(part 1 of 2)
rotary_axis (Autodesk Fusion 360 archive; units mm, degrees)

design "assy_rotary_axis" references "rotary_barrel", "PP_TRNS_GT2-Pulley-20T-6mm", "HW_M5x10-FHCS", "PP_SWTC_Omron-V154", "HW_M3x8-FHCS", "HW_M3x16-SHCS", "circuit_mount_stepper_simple", "PP_BRNG_6808-40x52x7", "HW_M3x50-SHCS", "HW_M3-Washer", "PP_ACTU_N17-Stepper"
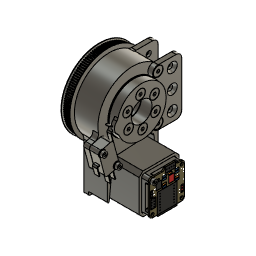
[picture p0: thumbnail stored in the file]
parameter "p_teeth" = 2
parameter "pd_pinion" = 12.7324 (= "nt_pinion * p_teeth / PI")
parameter "pd_drive" = 79.5775 (= "nt_drive * p_teeth / PI")
parameter "c_dist_manuel" = 58
parameter "d63" = 60
sketch "Sketch1" plane through (0, 0, 0) normal (0, 1, 0) x axis (1, 0, 0)
  line L1 (7, 26) -> (0, 26)
  line L2 (7, 20) -> (7, 26)
  line L3 (0, 20) -> (7, 20)
  line L4 (0, 26) -> (0, 20)
  line L5 (25, 20) -> (18, 20)
  line L6 (25, 26) -> (25, 20)
  line L7 (18, 26) -> (25, 26)
  line L8 (18, 20) -> (18, 26)
  line L9 (22.786, 0) -> (0, 0)
  line L10 (-50.1, 36.85) -> (19.9, 36.85)
  line L11 (-50.1, 79.15) -> (-50.1, 36.85)
  line L12 (19.9, 79.15) -> (-50.1, 79.15)
  line L13 (19.9, 36.85) -> (19.9, 79.15)
  line L14 (-50.1, 58) -> (19.9, 58)
  line L15 (25, 37.05) -> (25, 26.05)
  line L16 (0, 26.05) -> (25, 26.05)
  line L17 (25, 37.05) -> (0, 37.05)
  line L18 (0, 37.05) -> (0, 26.05)
  line L19 (7.5, 25.05) -> (6.5, 26.05)
  line L20 (17.5, 25.05) -> (7.5, 25.05)
  line L21 (18.5, 26.05) -> (17.5, 25.05)
  point P6 (18, 20)
  point P1 (0, 0)
  point P10 (0, 0)
  point P16 (19.9, 58)
  point P17 (-50.1, 58)
  point P21 (0, 37.05)
  point P23 (0, 37.05)
  point P18 (25, 26.05)
  point P19 (25, 26.05)
  point P8 (25, 26)
  point P2 (0, 26)
  point P24 (6.5, 26.05)
  point P27 (18.5, 26.05)
  point P4 (7, 20)
  point P5 (0, 20)
  point P12 (19.9, 36.85)
  point P15 (19.9, 79.15)
  point P13 (-50.1, 36.85)
  point P9 (18, 26)
  point P20 (0, 26.05)
  point P22 (25, 37.05)
  point P3 (7, 26)
  horizontal L1
  vertical L2
  horizontal L3
  horizontal L5
  vertical L6
  horizontal L7
  vertical L8
  equal L3 L5
  coincident L3 P6
  coincident P1 L4
  equal L2 L8
  coincident P1 P10
  horizontal L9
  horizontal L10
  vertical L11
  horizontal L12
  midpoint L13 P16
  midpoint L11 P17
  vertical L4
  vertical L15
  vertical L13
  perpendicular L2 L16
  perpendicular L13 L17
  perpendicular L10 L18
  coincident P21 P23
  coincident P18 P19
  coincident P8 L15
  coincident P2 L18
  coincident L16 P24
  parallel L1 L20
  coincident L16 P27
  dimension "d5" distance P4 P5 = 7
  dimension "d6" distance P1 L1 = 26 (= "( 52 / 2 ) * 1 mm")
  dimension "d7" distance P1 P5 = 20 (= "( 40 / 2 ) * 1 mm")
  dimension "d32" distance P12 P15 = 42.3
  dimension "d33" distance P1 P17 = 58 (= "c_dist_manuel")
  dimension "d34" distance P12 P13 = 70
  dimension "d61" distance P4 P6 = 11
  dimension "d140" distance P9 L16 = 0.05
  dimension "d141" distance P20 P23 = 11
  dimension "d150" distance L13 P22 = 5.1
  dimension "d259" angle L19 L20 = 45
  dimension "d260" distance P3 P24 = 0.5
  dimension "d261" distance L16 L20 = 1
  dimension "d262" angle L20 L21 = 45
  dimension "d263" distance L8 P27 = 0.5 (= "d260")
  dimension "d357" distance P18 L18 = 25
revolve "Revolve6" sketch "Sketch1" AlongAngle 360
sketch "Sketch6" plane through (0, 0, 0) normal (1, 0, 0) x axis (0, 1, 0)
  line L1 (21.15, -36.85) -> (-21.15, -36.85)
  line L2 (21.15, -79.15) -> (21.15, -36.85)
  line L3 (-21.15, -79.15) -> (21.15, -79.15)
  line L4 (-21.15, -36.85) -> (-21.15, -79.15)
  line L5 (21.15, -79.15) -> (-21.15, -36.85)
  line L6 (-21.15, -79.15) -> (21.15, -36.85)
  line L7 (0, 0) -> (0, -58)
  line L8 (15.5, -42.5) -> (-15.5, -42.5)
  line L9 (15.5, -73.5) -> (15.5, -42.5)
  line L10 (-15.5, -73.5) -> (15.5, -73.5)
  line L11 (-15.5, -42.5) -> (-15.5, -73.5)
  line L12 (15.4393, -40.5607) -> (-15.5, -42.5)
  line L13 (17.3786, -71.5) -> (-15.5, -42.5)
  line L14 (-13.5607, -73.4393) -> (-15.5, -42.5)
  line L15 (-15.5, -42.5) -> (12.1767, -76.5)
  line L16 (-15.5, -42.5) -> (-18.6616, -73.3384)
  line L17 (-15.5, -42.5) -> (15.3384, -45.6616)
  line L18 (12.4957, -82.7149) -> (-25.4068, -78.8291)
  line L19 (-21.0864, -36.6881) -> (-25.4068, -78.8291)
  line L20 (27, -33.674) -> (-21.0864, -36.6881)
  line L21 (-27, -78.6657) -> (-25.4068, -78.8291)
  line L22 (-27, -25.3713) -> (-27, -78.6657)
  line L23 (24.7149, -70.4957) -> (22.4249, -33.9608)
  line L24 (27, -25.3713) -> (27, -66.8875)
  line L25 (-43.1948, -16.2223) -> (-37.449, -37.6658)
  line L26 (-33.2458, -13.5564) -> (-43.1948, -16.2223)
  line L27 (-27.5, -35) -> (-33.2458, -13.5564)
  line L28 (-37.449, -37.6658) -> (-27.5, -35)
  line L29 (-46.8691, -14.101) -> (-39.5704, -41.3401)
  line L30 (-35.373, -11.0206) -> (-46.8691, -14.101)
  line L31 (-27, -37.9719) -> (-39.5704, -41.3401)
  arc A1 centre (-15.5, -42.5) radius 32.75 clockwise from (17.1859, -40.4512) to (17.0792, -45.8401)
  arc A2 centre (15.3384, -45.6616) radius 1.75 clockwise from (17.0792, -45.8401) to (13.5975, -45.4832)
  arc A3 centre (-15.5, -42.5) radius 29.25 clockwise from (13.6927, -40.6702) to (13.5975, -45.4832)
  arc A4 centre (15.4393, -40.5607) radius 1.75 clockwise from (13.6927, -40.6702) to (17.1859, -40.4512)
  arc A5 centre (-15.5, -42.5) radius 31 clockwise from (15.4393, -40.5607) to (15.3384, -45.6616)
  arc A6 centre (-15.5, -42.5) radius 33.0203 clockwise from (9.2638, -64.3425) to (5.3458, -68.1085)
  arc A7 centre (-1.6616, -59.5) radius 11.1 clockwise from (5.3458, -68.1085) to (-8.6691, -50.8915)
  arc A8 centre (-15.5, -42.5) radius 10.8203 clockwise from (-7.3852, -49.6575) to (-8.6691, -50.8915)
  arc A9 centre (0.9393, -57) radius 11.1 clockwise from (-7.3852, -49.6575) to (9.2638, -64.3425)
  arc A10 centre (-15.5, -42.5) radius 21.9203 clockwise from (0.9393, -57) to (-1.6616, -59.5)
  arc A11 centre (-15.5, -42.5) radius 45.5906 clockwise from (18.691, -72.6576) to (13.2815, -77.8572)
  arc A12 centre (12.1767, -76.5) radius 1.75 clockwise from (13.2815, -77.8572) to (11.0719, -75.1428)
  arc A13 centre (-15.5, -42.5) radius 42.0906 clockwise from (16.0661, -70.3424) to (11.0719, -75.1428)
  arc A14 centre (17.3786, -71.5) radius 1.75 clockwise from (16.0661, -70.3424) to (18.691, -72.6576)
  arc A15 centre (-15.5, -42.5) radius 43.8406 clockwise from (17.3786, -71.5) to (12.1767, -76.5)
  arc A16 centre (-15.5, -42.5) radius 32.75 clockwise from (-13.4512, -75.1859) to (-18.8401, -75.0792)
  arc A17 centre (-18.6616, -73.3384) radius 1.75 clockwise from (-18.8401, -75.0792) to (-18.4832, -71.5975)
  arc A18 centre (-15.5, -42.5) radius 29.25 clockwise from (-13.6702, -71.6927) to (-18.4832, -71.5975)
  arc A19 centre (-13.5607, -73.4393) radius 1.75 clockwise from (-13.6702, -71.6927) to (-13.4512, -75.1859)
  arc A20 centre (-15.5, -42.5) radius 31 clockwise from (-13.5607, -73.4393) to (-18.6616, -73.3384)
  circle C1 centre (-15.5, -42.5) radius 1.75
  arc A21 centre (-15.5, -42.5) radius 49 clockwise from (24.7149, -70.4957) to (12.4957, -82.7149)
  arc A22 centre (-15.5, -42.5) radius 49 clockwise from (27, -66.8875) to (24.7149, -70.4957)
  circle C2 centre (0, 0) radius 39.7887
  circle C3 centre (0, 0) radius 26.05
  circle C4 centre (0, 0) radius 37.05
  circle C5 centre (-27.5, -35) radius 1.25
  circle C6 centre (-43.1948, -16.2223) radius 1.25
  circle C7 centre (-43.1948, -16.2223) radius 3
  point P6 (0, -58)
  point P8 (0, -58)
  point P7 (0, 0)
  point P9 (0, 0)
  point P12 (15.5, -73.5)
  point P10 (-15.5, -42.5)
  point P13 (-15.5, -73.5)
  point P20 (-15.5, -42.5)
  point P27 (-15.5, -42.5)
  point P34 (-15.5, -42.5)
  point P41 (-15.5, -42.5)
  point P43 (-15.5, -42.5)
  point P18 (15.4393, -40.5607)
  point P44 (15.4393, -40.5607)
  point P42 (-15.5, -42.5)
  point P45 (-15.5, -42.5)
  point P32 (17.3786, -71.5)
  point P46 (17.3786, -71.5)
  point P47 (-15.5, -42.5)
  point P39 (-13.5607, -73.4393)
  point P48 (-13.5607, -73.4393)
  point P11 (15.5, -42.5)
  point P25 (0.9393, -57)
  point P33 (12.1767, -76.5)
  point P49 (12.1767, -76.5)
  point P50 (-15.5, -42.5)
  point P40 (-18.6616, -73.3384)
  point P51 (-18.6616, -73.3384)
  point P52 (-15.5, -42.5)
  point P19 (15.3384, -45.6616)
  point P53 (15.3384, -45.6616)
  point P54 (-15.5, -42.5)
  point P26 (-1.6616, -59.5)
  point P57 (-15.5, -42.5)
  point P60 (-21.0864, -36.6881)
  point P64 (22.4249, -33.9608)
  point P66 (19.1482, -77.1482)
  point P58 (24.7149, -70.4957)
  point P65 (24.7149, -70.4957)
  point P61 (27, -33.674)
  point P69 (-15.5, -42.5)
  point P67 (27, -66.8875)
  point P70 (27, -66.8875)
  point P71 (0, 0)
  point P68 (27, -25.3713)
  point P63 (-27, -25.3713)
  point P59 (-21.0864, -36.6881)
  point P76 (-27.5, -35)
  point P77 (-27.5, -35)
  point P74 (-43.1948, -16.2223)
  point P78 (-43.1948, -16.2223)
  point P80 (-35.373, -11.0206)
  point P83 (-27, -37.9719)
  point P4 (21.15, -79.15)
  point P5 (-21.15, -79.15)
  point P1 (0, 0)
  point P73 (-37.449, -37.6658)
  point P75 (-33.2458, -13.5564)
  point P81 (-43.1948, -16.2223)
  horizontal L1
  perpendicular L1 L2
  parallel L1 L3
  parallel L2 L4
  coincident L5 P6
  coincident L6 P6
  equal L2 L3
  coincident P6 P8
  coincident P7 P9
  vertical L7
  horizontal L8
  vertical L9
  horizontal L10
  vertical L11
  coincident L5 P12
  coincident L5 P10
  coincident L6 P13
  tangent A1 A2
  tangent A2 A3
  tangent A3 A4
  tangent A1 A4
  coincident P10 P20
  tangent A6 A7
  tangent A7 A8
  tangent A8 A9
  tangent A6 A9
  coincident P20 P27
  tangent A11 A12
  tangent A12 A13
  tangent A13 A14
  tangent A11 A14
  coincident P27 P34
  tangent A16 A17
  tangent A17 A18
  tangent A18 A19
  tangent A16 A19
  coincident P34 P41
  concentric A11 C1
  coincident P34 P43
  coincident P18 P44
  coincident P42 P45
  coincident P32 P46
  coincident P41 P47
  coincident P39 P48
  coincident P11 A5
  coincident P6 A10
  coincident P13 A20
  coincident P12 A15
  coincident P25 L13
  coincident P33 P49
  coincident P20 P50
  coincident P40 P51
  coincident P27 P52
  coincident P19 P53
  coincident P20 P54
  equal A4 A14
  equal A14 A19
  equal A19 C1
  coincident P26 L15
  perpendicular L12 L14
  perpendicular L16 L17
  parallel L17 L18
  coincident P42 P57
  parallel L16 L19
  coincident L19 P60
  parallel L12 L20
  perpendicular L19 L21
  vertical L22
  coincident L20 P64
  perpendicular L20 L23
  midpoint A21 P66
  coincident L5 P66
  coincident P58 P65
  vertical L24
  coincident P61 L24
  coincident P57 P69
  coincident P67 P70
  coincident P7 P71
  coincident P68 C4
  coincident P63 C4
  coincident P59 P60
  perpendicular L25 L26
  parallel L25 L27
  parallel L26 L28
  coincident P76 P77
  coincident P74 P78
  equal C5 C6
  perpendicular L26 L29
  coincident C4 P80
  perpendicular L29 L30
  concentric C6 C7
  coincident L22 P83
  perpendicular L29 L31
  dimension "d151" distance P6 P7 = 58 (= "c_dist_manuel")
  dimension "d152" distance P4 P5 = 42.3
  dimension "d153" distance P10 P11 = 31
  dimension "d154" diameter C1 = 3.5
  dimension "d156" radius A9 = 11.1 (= "( 22.2 / 2 ) * 1 mm")
  dimension "d157" distance P6 P25 = 1
  dimension "d158" distance P6 P26 = 1.5
  dimension "d159" angle L15 L17 = 45
  dimension "d160" radius A21 = 49
  dimension "d161" distance P40 L18 = 6.15 (= "( ( 42.3 - 31 ) / 2 ) * 1 mm + 0.5 mm")
  dimension "d162" distance L16 L19 = 6.15 (= "d161")
  dimension "d163" angle L12 L13 = 45
  dimension "d164" distance P20 L20 = 6.15 (= "d161")
  dimension "d166" distance P9 L22 = 27
  dimension "d167" distance P1 L24 = 27
  dimension "d264" diameter C2 = 79.5775 (= "pd_drive")
  dimension "d286" distance P73 P74 = 22.2
  dimension "d288" distance P74 P75 = 10.3
  dimension "d289" diameter C6 = 2.5
  dimension "d290" angle L7 L27 = 15
  dimension "d291" distance P71 P77 = 35
  dimension "d292" distance P1 P77 = 27.5
  dimension "d293" diameter C7 = 6
  dimension "d294" distance L29 P81 = 3
  dimension "d295" distance L30 P81 = 3 (= "d294")
  dimension "d303" distance P73 L31 = 3 (= "d294")
extrude "Extrude8" add sketch "Sketch6" profile of L19 L20 L21 L22 L23 L24 A22 C4 to an object
extrude "Extrude20" cut sketch "Sketch6" profile of L20 C4 to an object
extrude "Extrude19" add sketch "Sketch6" profile of A1 A2 A3 A4 A6 A7 A8 A9 A11 A12 A13 A14 A16 A17 A18 A19 C1 L18 A21 L19 L20 L23 along normal blind 5
chamfer "Chamfer4" distance 1.5
extrude "Extrude21" sketch "Sketch6" profile of L22 C4 C5 C6 L29 L30 L31 blind -6
extrude "Extrude22" sketch "Sketch6" profile of L22 C5 to an object offset 0.5
chamfer "Chamfer5" distance 1.25
chamfer "Chamfer6" distance 0.5
sketch "Sketch10" plane through (0, 0, 0) normal (-1, 0, 0) x axis (0, -1, 0)
  line L1 (27, -78.6657) -> (-12.4957, -82.7149)
  line L2 (27, -25.3713) -> (27, -78.6657)
  line L3 (-27, -66.8875) -> (-27, -25.3713)
  line L4 (-27, 50) -> (-47, 50)
  line L5 (-27, -90) -> (-27, 50)
  line L6 (-47, -90) -> (-27, -90)
  line L7 (-47, 50) -> (-47, -90)
  line L8 (-37, -90) -> (-37, 50)
  line L9 (-21.7417, 30) -> (-47, 30)
  line L10 (-47, -30) -> (-27, -30)
  line L11 (-18.6542, -30) -> (-27, -30)
  line L12 (-14.0196, -22.5467) -> (-18.6542, -30)
  line L13 (-27, 0) -> (0, 0)
  line L14 (-18.6542, 30) -> (-14.0196, 22.5467)
  line L15 (-21.7417, 30) -> (-18.6542, 30)
  circle C1 centre (15.5, -42.5) radius 3.25
  arc A1 centre (15.5, -42.5) radius 40.5906 clockwise from (-10.125, -73.9795) to (-14.9412, -69.3502)
  arc A2 centre (-12.1767, -76.5) radius 3.25 clockwise from (-10.125, -73.9795) to (-14.2284, -79.0205)
  arc A3 centre (15.5, -42.5) radius 47.0906 clockwise from (-14.2284, -79.0205) to (-19.8159, -73.6498)
  arc A4 centre (-17.3786, -71.5) radius 3.25 clockwise from (-19.8159, -73.6498) to (-14.9412, -69.3502)
  arc A5 centre (0, 0) radius 37.05 clockwise from (-27, -25.3713) to (27, -25.3713)
  arc A6 centre (15.5, -42.5) radius 49 clockwise from (-12.4957, -82.7149) to (-27, -66.8875)
  arc A7 centre (1.6616, -59.5) radius 11.1 clockwise from (8.6691, -50.8915) to (-5.3458, -68.1085)
  arc A8 centre (15.5, -42.5) radius 33.0203 clockwise from (-5.3458, -68.1085) to (-9.2638, -64.3425)
  arc A9 centre (-0.9393, -57) radius 11.1 clockwise from (-9.2638, -64.3425) to (7.3852, -49.6575)
  arc A10 centre (15.5, -42.5) radius 10.8203 clockwise from (8.6691, -50.8915) to (7.3852, -49.6575)
  arc A11 centre (15.5, -42.5) radius 27.75 clockwise from (-12.1053, -45.3302) to (-12.1956, -40.764)
  arc A12 centre (-15.3384, -45.6616) radius 3.25 clockwise from (-12.1053, -45.3302) to (-18.5714, -45.9931)
  arc A13 centre (15.5, -42.5) radius 34.25 clockwise from (-18.5714, -45.9931) to (-18.6829, -40.3574)
  arc A14 centre (-15.4393, -40.5607) radius 3.25 clockwise from (-18.6829, -40.3574) to (-12.1956, -40.764)
  arc A15 centre (13.5607, -73.4393) radius 3.25 clockwise from (13.3574, -76.6829) to (13.764, -70.1956)
  arc A16 centre (15.5, -42.5) radius 27.75 clockwise from (18.3302, -70.1053) to (13.764, -70.1956)
  arc A17 centre (18.6616, -73.3384) radius 3.25 clockwise from (18.3302, -70.1053) to (18.9931, -76.5714)
  arc A18 centre (15.5, -42.5) radius 34.25 clockwise from (18.9931, -76.5714) to (13.3574, -76.6829)
  circle C2 centre (0, 0) radius 26.55
  circle C3 centre (-37, -20) radius 2.75
  circle C4 centre (-37, 0) radius 2.75
  circle C5 centre (-37, 20) radius 2.75
  circle C6 centre (-21.9887, -24) radius 2.75
  circle C7 centre (-21.9887, -24) radius 2.2
  circle C8 centre (-21.9887, -24) radius 6
  circle C9 centre (-21.9887, 24) radius 2.75
  circle C10 centre (-21.9887, 24) radius 2.2
  circle C11 centre (-21.9887, 24) radius 6
  point P12 (-27, -25.3713)
  point P37 (-37, 50)
  point P38 (-37, -90)
  point P39 (-47, 30)
  point P40 (-21.7417, 30)
  point P41 (-27, -30)
  point P42 (-47, -30)
  point P43 (-37, -20)
  point P44 (-37, 0)
  point P45 (-37, 20)
  point P49 (-14.0196, -22.5467)
  point P1 (0, 0)
  point P50 (0, 0)
  point P51 (-27, 0)
  point P56 (-14.0196, 22.5467)
  point P58 (-21.7417, 30)
  point P33 (-47, 50)
  point P34 (-27, 50)
  point P13 (0, 0)
  horizontal L4
  vertical L5
  horizontal L6
  vertical L7
  coincident P12 L5
  midpoint L4 P37
  midpoint L6 P38
  coincident L7 P39
  coincident A5 P40
  perpendicular L7 L9
  coincident L5 P41
  coincident L7 P42
  perpendicular L7 L10
  coincident L8 P43
  coincident L8 P44
  coincident L8 P45
  equal C4 C5
  equal C3 C4
  concentric C6 C7
  perpendicular L5 L11
  coincident C2 P49
  coincident P1 L12
  coincident P1 P50
  coincident L5 P51
  perpendicular L5 L13
  concentric C7 C8
  equal C3 C6
  symmetric C6 L13 C9
  symmetric C7 L13 C10
  symmetric L13 C8 C11
  coincident C2 P56
  horizontal L15
  coincident P40 P58
  tangent C11 L14
  coincident P1 L14
  tangent L10 C8
  tangent C2 C8
  tangent L12 C8
  dimension "d358" distance P33 P34 = 20
  dimension "d359" distance P13 L4 = 50
  dimension "d360" distance P13 L6 = 90
  dimension "d361" distance P13 P39 = 30
  dimension "d368" diameter C3 = 5.5
  dimension "d369" distance P43 P44 = 20
  dimension "d370" distance P44 P45 = 20
  dimension "d371" distance P39 P45 = 10
  dimension "d372" distance L10 P43 = 10
  dimension "d375" angle L12 L13 = 58.126
  dimension "d376" diameter C7 = 4.4
  dimension "d377" diameter C8 = 12
extrude "Extrude23" cut sketch "Sketch10" profile of A5 L3 L5 L7 L9 L10 no distance stored from offset -5
extrude "Extrude24" add sketch "Sketch10" profile of A5 L3 L5 L7 L9 L10 C3 C4 C5 against normal blind 5
extrude "Extrude25" cut sketch "Sketch10" profile of A5 C3 C4 C5 no distance stored
chamfer "Chamfer7" distance 2.5
extrude "Extrude26" cut sketch "Sketch10" profile of C7 C10 no distance stored
extrude "Extrude27" sketch "Sketch10" profile of A5 L3 C2 L5 L7 L9 L10 C3 C4 C5 C6 L11 L12 C9 L14 L15 blind -5 from offset -0.1 bodies "rotary_body_cap"
chamfer "Chamfer8" distance 2.5
chamfer "Chamfer9" distance 2.5
fillet "Fillet18" radius 6
fillet "Fillet19" radius 6
component_insert "Component Insert9"
component_insert "Component Insert10"
joint "Assemble7" alignAngle 180 alignOffsetX 0 alignOffsetY 0 alignOffsetZ 0
joint "Assemble8" alignAngle 180 alignOffsetX 0 alignOffsetY 0 alignOffsetZ 0
component_insert "Component Insert1"
joint "Assemble1" alignAngle 0 alignOffsetX 0 alignOffsetY 0 alignOffsetZ 0
component_insert "Component Insert6"
joint "Assemble4" alignAngle 180 alignOffsetX 0 alignOffsetY 0 alignOffsetZ 0
component_insert "Component Insert7"
joint "Assemble5" alignAngle -195 alignOffsetX 0 alignOffsetY 0 alignOffsetZ 0
component_insert "Component Insert8"
joint "Assemble6" alignAngle 0 alignOffsetX 0 alignOffsetY 0 alignOffsetZ -2.5
component_insert "Component Insert11"
component_insert "Component Insert12"
component_insert "Component Insert13"
component_insert "Component Insert14"
joint "Assemble9" alignAngle 180 alignOffsetX 0 alignOffsetY 0 alignOffsetZ 0
joint "Assemble10" alignAngle 180 alignOffsetX 0 alignOffsetY 0 alignOffsetZ -5
joint "Assemble11" alignAngle 180 alignOffsetX 0 alignOffsetY 0 alignOffsetZ -5
joint "Assemble12" alignAngle 180 alignOffsetX 0 alignOffsetY 0 alignOffsetZ -5
component_insert "Component Insert15"
component_insert "Component Insert16"
joint "Assemble13" alignAngle 0 alignOffsetX 0 alignOffsetY 0 alignOffsetZ 0
joint "Assemble14" alignAngle 0 alignOffsetX 0 alignOffsetY 0 alignOffsetZ 0
component_insert "Component Insert17"
component_insert "Component Insert18"
joint "Assemble15" alignAngle 0 alignOffsetX 0 alignOffsetY 0 alignOffsetZ 0
joint "Assemble16" alignAngle 0 alignOffsetX 0 alignOffsetY 0 alignOffsetZ 0
fillet "Fillet10" radius 4
fillet "Fillet11" radius 10
fillet "Fillet12" radius 1
fillet "Fillet13" radius 5
fillet "Fillet14" radius 1
fillet "Fillet15" radius 1
fillet "Fillet16" radius 3
fillet "Fillet17" radius 5
fillet "Fillet20" radius 6
component_insert "Component Insert19"
joint "Assemble17" alignAngle 90 alignOffsetX 0 alignOffsetY 0 alignOffsetZ 0
component_insert "Component Insert20"
component_insert "Component Insert21"
joint "Assemble18" alignAngle 0 alignOffsetX 0 alignOffsetY 0 alignOffsetZ 0
joint "Assemble19" alignAngle 0 alignOffsetX 0 alignOffsetY 0 alignOffsetZ 0
component_insert "Component Insert23"
joint "Assemble20" alignAngle 90 alignOffsetX 0 alignOffsetY 0 alignOffsetZ 0
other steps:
joint_origin "JointOrigin5"
joint_origin "JointOrigin6"
joint_origin "JointOrigin9"
joint_origin "JointOrigin10"
joint_origin "JointOrigin11"
joint_origin "JointOrigin12"
joint_origin "JointOrigin13"
joint_origin "JointOrigin14"
named bodies: "rotary_body", "rotary_body_cap"

design "rotary_barrel" references "HW_M5x20-FHCS"
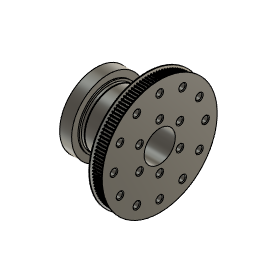
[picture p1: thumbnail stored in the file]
parameter "p_teeth" = 2
parameter "pd_pinion" = 12.7324 (= "nt_pinion * p_teeth / PI")
parameter "pd_drive" = 79.5775 (= "nt_drive * p_teeth / PI")
parameter "c_dist_manuel" = 75
sketch "Sketch1" plane through (0, 0, 0) normal (0, 1, 0) x axis (1, 0, 0)
  line L1 (7, 26) -> (0, 26)
  line L2 (7, 20) -> (7, 26)
  line L3 (0, 20) -> (7, 20)
  line L4 (0, 26) -> (0, 20)
  line L5 (25, 20) -> (18, 20)
  line L6 (25, 26) -> (25, 20)
  line L7 (18, 26) -> (25, 26)
  line L8 (18, 20) -> (18, 26)
  line L9 (35.5, 11.05) -> (2.5, 11.05)
  line L10 (35.5, 39.7887) -> (26, 39.7887)
  line L11 (26, 21.5) -> (25, 21.5)
  line L12 (26, 40.7887) -> (26, 21.5)
  line L13 (26.5, 40.7887) -> (26, 40.7887)
  line L14 (27.9434, 38.2887) -> (26.5, 40.7887)
  line L15 (33.5566, 38.2887) -> (27.9434, 38.2887)
  line L16 (35, 40.7887) -> (33.5566, 38.2887)
  line L17 (30.75, 38.2887) -> (30.75, 39.7887)
  line L18 (35, 38.2887) -> (35, 40.7887)
  line L19 (33.5566, 38.2887) -> (35, 38.2887)
  line L20 (26, 38.2887) -> (27.9434, 38.2887)
  line L21 (25, 20.05) -> (25, 21.5)
  line L22 (2.5, 20.05) -> (25, 20.05)
  line L23 (2.5, 11.05) -> (2.5, 20.05)
  line L24 (26, 38.2887) -> (26, 21.5)
  line L25 (35.5, 11.05) -> (35.5, 39.7887)
  line L26 (2, 11.05) -> (2, 20.05)
  line L27 (-9.5, 11.05) -> (2, 11.05)
  line L28 (-9.5, 26) -> (-9.5, 11.05)
  line L29 (-1, 26) -> (-9.5, 26)
  line L30 (-1, 21.5) -> (-1, 26)
  line L31 (0, 21.5) -> (-1, 21.5)
  line L32 (0, 20.05) -> (0, 21.5)
  line L33 (2, 20.05) -> (0, 20.05)
  line L34 (35.5, 40.7887) -> (35, 40.7887)
  line L35 (35.5, 39.7887) -> (35.5, 40.7887)
  line L36 (35.5, 14.35) -> (2.5, 14.35)
  line L37 (2.5, 16.55) -> (35.5, 16.55)
  line L38 (-9.5, 16.55) -> (2, 16.55)
  line L39 (-7.025, 13.925) -> (-9.5, 11.45)
  line L40 (2, 13.925) -> (-7.025, 13.925)
  line L41 (26, 32.5) -> (35.5, 32.5)
  line L42 (35.5, 34.7) -> (26, 34.7)
  point P6 (18, 20)
  point P1 (0, 0)
  point P13 (25, 21.5)
  point P20 (30.75, 39.7887)
  point P21 (30.75, 38.2887)
  point P11 (26, 39.7887)
  point P22 (27.2217, 39.5387)
  point P23 (34.2783, 39.5387)
  point P18 (33.5566, 38.2887)
  point P25 (33.5566, 38.2887)
  point P26 (26, 38.2887)
  point P27 (25, 20.05)
  point P10 (35.5, 11.05)
  point P30 (35.5, 11.05)
  point P31 (2, 20.05)
  point P39 (2, 20.05)
  point P32 (2, 11.05)
  point P5 (0, 20)
  point P12 (35.5, 39.7887)
  point P41 (35.5, 39.7887)
  point P42 (2.5, 14.35)
  point P45 (2.5, 16.55)
  point P46 (2, 16.55)
  point P47 (-9.5, 16.55)
  point P48 (-9.5, 11.45)
  point P50 (2, 13.925)
  point P51 (35.5, 32.5)
  point P54 (35.5, 34.7)
  point P53 (26, 34.7)
  point P52 (26, 32.5)
  point P44 (35.5, 16.55)
  point P43 (35.5, 14.35)
  point P4 (7, 20)
  point P14 (26, 21.5)
  point P15 (26, 40.7887)
  point P16 (26.5, 40.7887)
  point P7 (25, 20)
  point P3 (7, 26)
  point P9 (18, 26)
  point P28 (2.5, 20.05)
  point P29 (2.5, 11.05)
  point P36 (-1, 21.5)
  point P37 (0, 21.5)
  point P19 (35, 40.7887)
  point P40 (35.5, 40.7887)
  point P33 (-9.5, 11.05)
  point P38 (0, 20.05)
  horizontal L1
  vertical L2
  horizontal L3
  horizontal L5
  vertical L6
  horizontal L7
  vertical L8
  equal L3 L5
  coincident L3 P6
  coincident P1 L4
  equal L2 L8
  horizontal L9
  vertical L4
  horizontal L10
  coincident L6 P13
  perpendicular L6 L11
  perpendicular L10 L12
  perpendicular L12 L13
  perpendicular L12 L15
  midpoint L10 P20
  midpoint L15 P21
  vertical L17
  coincident P11 L12
  midpoint L14 P22
  midpoint L16 P23
  perpendicular L18 L19
  coincident P18 P25
  coincident L12 P26
  perpendicular L12 L20
  coincident L6 P27
  perpendicular L4 L22
  perpendicular L9 L23
  equal L14 L16
  vertical L18
  perpendicular L10 L25
  coincident P10 P30
  perpendicular L5 L26
  perpendicular L9 L28
  perpendicular L28 L29
  perpendicular L29 L30
  perpendicular L30 L31
  perpendicular L31 L32
  perpendicular L30 L33
  coincident P31 P39
  coincident L22 P31
  coincident L9 P32
  coincident P5 L32
  coincident P13 L31
  horizontal L27
  perpendicular L18 L34
  perpendicular L34 L35
  coincident P12 P41
  coincident L23 P42
  perpendicular L23 L36
  coincident L23 P45
  perpendicular L23 L37
  coincident L26 P46
  coincident L28 P47
  perpendicular L28 L38
  coincident L28 P48
  coincident L26 P50
  perpendicular L26 L40
  coincident P45 L38
  coincident L25 P51
  perpendicular L25 L41
  coincident L25 P54
  perpendicular L25 L42
  coincident L12 P53
  coincident L12 P52
  coincident L25 P44
  coincident L25 P43
  dimension "d5" distance P4 P5 = 7
  dimension "d6" distance P1 L1 = 26 (= "( 52 / 2 ) * 1 mm")
  dimension "d7" distance P1 P5 = 20 (= "( 40 / 2 ) * 1 mm")
  dimension "d62" distance P1 L10 = 39.7887 (= "pd_drive / 2")
  dimension "d63" angle L13 L14 = 60
  dimension "d66" distance P13 P14 = 1
  dimension "d67" distance L10 L13 = 1
  dimension "d68" distance L10 L15 = 1.5
  dimension "d69" distance P15 P16 = 0.5
  dimension "d71" distance P7 L11 = 1.5
  dimension "d72" distance P6 L22 = 0.05
  dimension "d81" angle L15 L16 = 120 (= "180 deg - d63")
  dimension "d133" distance P15 L18 = 9
  dimension "d223" distance P3 P9 = 11
  dimension "d224" distance L23 P32 = 0.5
  dimension "d225" distance P28 P29 = 9
  dimension "d227" distance P36 P37 = 1
  dimension "d228" distance P1 L29 = 26 (= "( 52 / 2 ) * 1 mm")
  dimension "d229" distance P19 P40 = 0.5
  dimension "d237" distance P10 L28 = 45
  dimension "d238" distance P32 P33 = 11.5
  dimension "d240" distance L36 P45 = 2.2 (= "( 4.4 / 2 ) * 1 mm")
  dimension "d242" distance L38 L40 = 2.625 (= "( 5.25 / 2 ) * 1 mm")
  dimension "d243" angle L39 L40 = 45
  dimension "d244" distance P47 P48 = 5.1 (= "( 10.2 / 2 ) * 1 mm")
  dimension "d245" distance P33 L38 = 5.5
  dimension "d250" distance L41 P54 = 2.2 (= "( 4.4 / 2 ) * 1 mm")
  dimension "d251" distance P1 L41 = 32.5
  dimension "d307" distance P13 P37 = 25
  dimension "d308" distance L26 P38 = 2
revolve "Revolve1" sketch "Sketch1" AlongAngle 360 bodies "rotary_barrel_toothed", "rotary_barrel_cap"
sketch "Sketch5" plane through (26, 0, 0) normal (-1, 0, 0) x axis (0, -1, 0)
  line L1 (0, -39.7887) -> (0, 0)
  line L2 (-0.9999, -39.7762) -> (0, 0)
  circle C1 centre (0, 0) radius 21.5
  circle C2 centre (0, 0) radius 39.7887
  circle C3 centre (0, 0) radius 39.5347
  arc A1 centre (0, -39.3347) radius 0.55 clockwise from (-0.4889, -39.0828) to (0, -38.7847)
  arc A2 centre (0.4, -39.5409) radius 1 clockwise from (-0.5899, -39.3991) to (-0.4889, -39.0828)
  arc A3 centre (-0.7384, -39.3778) radius 0.15 clockwise from (-0.5899, -39.3991) to (-0.7412, -39.5278)
  point P1 (0, 0)
  point P4 (0, 0)
  point P5 (0, -39.7887)
  point P3 (0, 0)
  point P6 (0, 0)
  point P7 (-0.9999, -39.7762)
  point P9 (0, -38.7847)
  point P13 (-0.7412, -39.5278)
  point P15 (0, -39.5347)
  point P8 (0, -39.3347)
  point P11 (0.4, -39.5409)
  concentric C1 C3
  coincident P1 P4
  coincident C2 P5
  vertical L1
  coincident P3 P6
  coincident C2 P7
  coincident L1 P9
  tangent A1 A2
  tangent A2 A3
  coincident C3 P13
  coincident L1 P15
  coincident C3 P15
  coincident L1 P8
  tangent C3 A3
  dimension "d116" distance C2 C3 = 0.254
  dimension "d117" angle L1 L2 = 1.44 (= "( 180 / nt_drive ) * 1 deg")
  dimension "d118" radius A1 = 0.55
  dimension "d119" radius A2 = 1
  dimension "d120" distance L1 P11 = 0.4
  dimension "d121" radius A3 = 0.15
  dimension "d122" distance P9 P15 = 0.75
extrude "Extrude6" new body sketch "Sketch5" profile of C2 C3 L1 L2 A1 A2 A3 to an object
offset_faces "OffsetFaces1" distance 0.05
mirror "Mirror2" mirrorStitchTolerance 0.1
circular_pattern "C-Pattern3" TotalAngle 360
combine "Combine3"
combine "Combine4"
revolve "Revolve5" sketch "Sketch1" AlongAngle 360
sketch "Sketch8" plane through (-9.5, 0, 0) normal (-1, 0, 0) x axis (0, -1, 0)
  line L1 (-29, 0) -> (0, 0)
  circle C1 centre (0, 0) radius 11.05
  circle C2 centre (0, 0) radius 26
  arc A1 centre (-21, 0) radius 8 clockwise from (-25.0714, -6.8865) to (-25.0714, 6.8865)
  point P4 (-25.0714, 6.8865)
  point P3 (-25.0714, -6.8865)
  point P1 (0, 0)
  point P6 (0, 0)
  point P8 (-26, 0)
  point P7 (-29, 0)
  point P5 (-21, 0)
  coincident C2 P4
  coincident C2 P3
  coincident P1 P6
  horizontal L1
  coincident L1 P8
  coincident C2 P8
  coincident A1 P7
  coincident P5 L1
  dimension "d231" distance P7 P8 = 3
  dimension "d232" radius A1 = 8
extrude "Extrude13" add sketch "Sketch8" profile of C2 A1 against normal blind 3.6
fillet "Fillet2" radius 5
revolve "Revolve7" sketch "Sketch1" AlongAngle 360
chamfer "Chamfer4" distance 0.5
circular_pattern "C-Pattern9" TotalAngle 360
revolve "Revolve8" sketch "Sketch1" AlongAngle 360
chamfer "Chamfer3" distance 0.5
circular_pattern "C-Pattern8" countU 12 TotalAngle 360
component_insert "Component Insert8"
component_insert "Component Insert9"
component_insert "Component Insert10"
component_insert "Component Insert11"
component_insert "Component Insert12"
component_insert "Component Insert13"
joint "Assemble19" alignAngle 0 alignOffsetX 0 alignOffsetY 0 alignOffsetZ 0
joint "Assemble20" alignAngle 0 alignOffsetX 0 alignOffsetY 0 alignOffsetZ 0
joint "Assemble21" alignAngle 0 alignOffsetX 0 alignOffsetY 0 alignOffsetZ 0
joint "Assemble22" alignAngle 0 alignOffsetX 0 alignOffsetY 0 alignOffsetZ 0
joint "Assemble23" alignAngle 0 alignOffsetX 0 alignOffsetY 0 alignOffsetZ 0
joint "Assemble24" alignAngle 0 alignOffsetX 0 alignOffsetY 0 alignOffsetZ 0
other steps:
joint_origin "JointOrigin19"
joint_origin "JointOrigin20"
joint_origin "JointOrigin22"
joint_origin "JointOrigin23"
joint_origin "JointOrigin24"
joint_origin "JointOrigin25"
named bodies: "rotary_barrel_toothed", "rotary_barrel_cap"

design "HW_M5x10-FHCS"
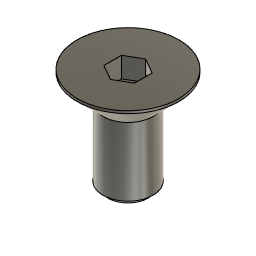
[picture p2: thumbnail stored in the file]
sketch "Sketch1" plane through (0, 0, 0) normal (0, 1, 0) x axis (1, 0, 0)
  line L1 (0, 10) -> (0, 0)
  line L2 (1.95, 10) -> (0, 10)
  line L3 (2.45, 9.5) -> (1.95, 10)
  line L4 (2.45, 2.8) -> (2.45, 9.5)
  line L5 (5, 0.25) -> (2.45, 2.8)
  line L6 (5, 0) -> (5, 0.25)
  line L7 (0, 0) -> (5, 0)
  point P1 (0, 0)
  point P2 (0, 0)
  point P9 (0, 0)
  point P3 (0, 10)
  point P4 (1.95, 10)
  point P8 (5, 0)
  point P7 (5, 0.25)
  coincident P1 P2
  vertical L1
  perpendicular L1 L2
  perpendicular L2 L4
  parallel L3 L5
  parallel L4 L6
  perpendicular L6 L7
  coincident P1 P9
  dimension "d1" distance P3 L4 = 2.45 (= "( 4.9 / 2 ) * 1 mm")
  dimension "d3" angle L2 L3 = 45
  dimension "d5" distance P4 L4 = 0.5
  dimension "d6" distance P2 P3 = 10
  dimension "d7" distance P8 P9 = 5 (= "( 10 / 2 ) * 1 mm")
  dimension "d9" distance P7 P8 = 0.25
revolve "Revolve1" sketch "Sketch1" AlongAngle 360
sketch "Sketch2" plane through (0, 0, 0) normal (0, 0, 1) x axis (-1, 0, 0)
  line L1 (0, -1.7321) -> (-1.5, -0.866)
  line L2 (1.5, -0.866) -> (0, -1.7321)
  line L3 (1.5, 0.866) -> (1.5, -0.866)
  line L4 (0, 1.7321) -> (1.5, 0.866)
  line L5 (-1.5, 0.866) -> (0, 1.7321)
  line L6 (-1.5, -0.866) -> (-1.5, 0.866)
  circle C1 centre (0, 0) radius 5
  point P1 (0, 0)
  point P9 (0, 0)
  coincident P1 P9
  vertical L6
  dimension "d12" distance L3 L6 = 3
extrude "Extrude1" cut sketch "Sketch2" profile of L1 L2 L3 L4 L5 L6 against normal blind 2

design "HW_M3x8-FHCS"
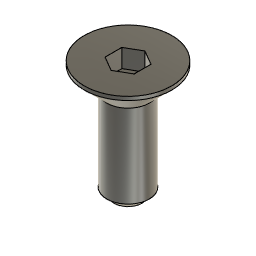
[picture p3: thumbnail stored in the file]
sketch "Sketch1" plane through (0, 0, 0) normal (0, 1, 0) x axis (1, 0, 0)
  line L1 (0, 8) -> (0, 0)
  line L2 (0.95, 8) -> (0, 8)
  line L3 (1.45, 7.5) -> (0.95, 8)
  line L4 (1.45, 1.8) -> (1.45, 7.5)
  line L5 (3, 0.25) -> (1.45, 1.8)
  line L6 (3, 0) -> (3, 0.25)
  line L7 (0, 0) -> (3, 0)
  point P1 (0, 0)
  point P2 (0, 0)
  point P9 (0, 0)
  point P3 (0, 8)
  point P4 (0.95, 8)
  point P8 (3, 0)
  point P7 (3, 0.25)
  coincident P1 P2
  vertical L1
  perpendicular L1 L2
  perpendicular L2 L4
  parallel L3 L5
  parallel L4 L6
  perpendicular L6 L7
  coincident P1 P9
  dimension "d1" distance P3 L4 = 1.45 (= "( 2.9 / 2 ) * 1 mm")
  dimension "d3" angle L2 L3 = 45
  dimension "d5" distance P4 L4 = 0.5
  dimension "d6" distance P2 P3 = 8
  dimension "d7" distance P8 P9 = 3 (= "( 6 / 2 ) * 1 mm")
  dimension "d9" distance P7 P8 = 0.25
revolve "Revolve1" sketch "Sketch1" AlongAngle 360
sketch "Sketch2" plane through (0, 0, 0) normal (0, 0, 1) x axis (-1, 0, 0)
  line L1 (0, -1.1547) -> (-1, -0.5774)
  line L2 (1, -0.5774) -> (0, -1.1547)
  line L3 (1, 0.5774) -> (1, -0.5774)
  line L4 (0, 1.1547) -> (1, 0.5774)
  line L5 (-1, 0.5774) -> (0, 1.1547)
  line L6 (-1, -0.5774) -> (-1, 0.5774)
  circle C1 centre (0, 0) radius 3
  point P1 (0, 0)
  point P9 (0, 0)
  coincident P1 P9
  vertical L6
  dimension "d12" distance L3 L6 = 2
extrude "Extrude1" cut sketch "Sketch2" profile of L1 L2 L3 L4 L5 L6 against normal blind 1.26

design "circuit_modular_stepper"
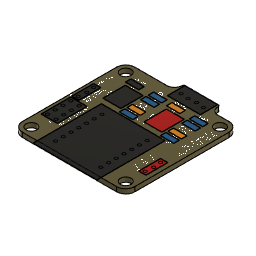
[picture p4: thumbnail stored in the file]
sketch "Outline" plane through (0, 0, 0) normal (0, 0, 1) x axis (1, 0, 0)
  line L1 (35, 1) -> (4, 1)
  line L2 (38, 35) -> (38, 4)
  line L3 (31, 38) -> (35, 38)
  line L4 (17.5, 41) -> (28.5, 41)
  line L5 (4, 38) -> (14.5, 38)
  line L6 (1, 4) -> (1, 35)
  arc A1 centre (4, 4) radius 3 clockwise from (4, 1) to (1, 4)
  arc A2 centre (35, 4) radius 3 clockwise from (38, 4) to (35, 1)
  arc A3 centre (35, 35) radius 3 clockwise from (35, 38) to (38, 35)
  arc A4 centre (31.25, 40.25) radius 2.2638 clockwise from (31, 38) to (29, 40.5)
  arc A5 centre (28.5, 40.5) radius 0.5 clockwise from (28.5, 41) to (29, 40.5)
  arc A6 centre (17.5, 40.5) radius 0.5 clockwise from (17, 40.5) to (17.5, 41)
  arc A7 centre (14.5, 40.5) radius 2.5 clockwise from (17, 40.5) to (14.5, 38)
  arc A8 centre (4, 35) radius 3 clockwise from (1, 35) to (4, 38)
canvas "Canvas1"
canvas "Canvas2"
pcbhole "PCBHole1" HoleDepth 1.606 HoleDiameter 3.5 TipAngle 10313.2
pcbhole "PCBHole2" HoleDepth 1.606 HoleDiameter 3.5 TipAngle 10313.2
pcbhole "PCBHole3" HoleDepth 1.606 HoleDiameter 3.5 TipAngle 10313.2
pcbhole "PCBHole4" HoleDepth 1.606 HoleDiameter 3.5 TipAngle 10313.2
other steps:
pcbextrude "PCBExtrude1"
pcbextrude "PCBExtrude1"
extrude "Extrude1" sketch "Outline" blind 1.5 bodies "Board"
box_primitive "BoxPrimitive1" DistanceX 7.1628 DistanceY 2.3368 DistanceZ 0.1 OffsetDistanceX 0 OffsetDistanceY 0
box_primitive "BoxPrimitive1" DistanceX 10.827 DistanceY 5.727 DistanceZ 0.1 OffsetDistanceX 0 OffsetDistanceY 0
box_primitive "BoxPrimitive1" DistanceX 5.353 DistanceY 9.7028 DistanceZ 0.1 OffsetDistanceX 0 OffsetDistanceY 0
box_primitive "BoxPrimitive1" DistanceX 4.4 DistanceY 1.8 DistanceZ 0.1 OffsetDistanceX 0 OffsetDistanceY 0
box_primitive "BoxPrimitive1" DistanceX 7.35 DistanceY 5.8597 DistanceZ 0.1 OffsetDistanceX 0 OffsetDistanceY 0
box_primitive "BoxPrimitive1" DistanceX 22.4638 DistanceY 20.955 DistanceZ 0.1 OffsetDistanceX 0 OffsetDistanceY 0
pcbextrude "PCBExtrude1"
pcbextrude "PCBExtrude2" bodies "CopperHoles"
create_component "CreateComponent1"
create_component "CreateComponent2"
create_component "CreateComponent3"
create_component "CreateComponent4"
create_component "CreateComponent1"
create_component "CreateComponent2"
create_component "CreateComponent3"
create_component "CreateComponent4"
create_component "CreateComponent5"
create_component "CreateComponent6"
as_built_joint "As-built1"
named bodies: "Board", "CopperHoles"

design "circuit_mount_stepper_simple" references "circuit_modular_stepper"
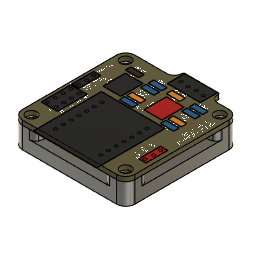
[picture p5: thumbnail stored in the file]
sketch "Sketch1" plane through (0, 0, 0) normal (0, 0, 1) x axis (1, 0, 0)
  line L1 (-18.5, 18.5) -> (18.5, 18.5)
  line L2 (-18.5, -18.5) -> (-18.5, 18.5)
  line L3 (18.5, -18.5) -> (-18.5, -18.5)
  line L4 (18.5, 18.5) -> (18.5, -18.5)
  line L5 (-18.5, -18.5) -> (18.5, 18.5)
  line L6 (18.5, -18.5) -> (-18.5, 18.5)
  line L7 (15.5, 15.5) -> (-15.5, 15.5)
  line L8 (15.5, -15.5) -> (15.5, 15.5)
  line L9 (-15.5, -15.5) -> (15.5, -15.5)
  line L10 (-15.5, 15.5) -> (-15.5, -15.5)
  circle C1 centre (15.5, 15.5) radius 1.7
  circle C2 centre (-15.5, 15.5) radius 1.7
  circle C3 centre (-15.5, -15.5) radius 1.7
  circle C4 centre (15.5, -15.5) radius 1.7
  circle C5 centre (-15.5, 15.5) radius 4.5
  circle C6 centre (15.5, 15.5) radius 4.5
  circle C7 centre (15.5, -15.5) radius 4.5
  circle C8 centre (-15.5, -15.5) radius 4.5
  circle C9 centre (0, 0) radius 15
  circle C10 centre (0, 0) radius 2.5
  circle C11 centre (0, 0) radius 4
  circle C12 centre (0, 0) radius 6.5
  point P6 (0, 0)
  point P1 (0, 0)
  point P9 (15.5, -15.5)
  point P7 (-15.5, 15.5)
  point P8 (15.5, 15.5)
  point P11 (15.5, 15.5)
  point P12 (-15.5, 15.5)
  point P10 (-15.5, -15.5)
  point P13 (-15.5, -15.5)
  point P14 (15.5, -15.5)
  point P19 (0, 0)
  point P21 (0, 0)
  point P2 (18.5, 18.5)
  point P3 (-18.5, 18.5)
  horizontal L1
  perpendicular L1 L2
  parallel L1 L3
  parallel L2 L4
  coincident L5 P6
  coincident L6 P6
  coincident P1 P6
  equal L1 L4
  horizontal L7
  vertical L8
  horizontal L9
  vertical L10
  coincident L6 P9
  coincident L6 P7
  coincident L5 P8
  equal C3 C4
  equal C1 C4
  equal C1 C2
  coincident P8 P11
  coincident P7 P12
  coincident P10 P13
  coincident P9 P14
  concentric C2 C5
  concentric C1 C6
  concentric C4 C7
  concentric C3 C8
  equal C5 C8
  equal C5 C6
  equal C6 C7
  coincident P1 P19
  concentric C9 C10
  coincident P1 P21
  concentric C9 C12
  dimension "d1" distance P7 P8 = 31
  dimension "d2" distance P2 P3 = 37
  dimension "d3" diameter C1 = 3.4
  dimension "d4" distance L4 P11 = 3
  dimension "d5" diameter C6 = 9
  dimension "d6" diameter C9 = 30
  dimension "d7" diameter C10 = 5
  dimension "d8" diameter C11 = 8
  dimension "d9" distance C11 C12 = 2.5
extrude "Extrude1" new body sketch "Sketch1" profile of L1 L2 L3 L4 C1 C2 C3 C4 C5 C6 C7 C8 along normal blind 7 bodies "circuit_mount_stepper_simple"
extrude "Extrude4" add sketch "Sketch1" profile of L1 L2 L3 L4 C5 C6 C7 C8 C9 to an object offset -3
chamfer "Chamfer4" distance 0.5
fillet "Fillet1" radius 3
fillet "Fillet2" radius 2
chamfer "Chamfer5" distance 0.5
component_insert "Component Insert"
joint "Assemble1" alignAngle 0 alignOffsetX 0 alignOffsetY 0 alignOffsetZ 0
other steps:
joint_origin "JointOrigin1"
named bodies: "circuit_mount_stepper_simple"

design "HW_M3x50-SHCS"
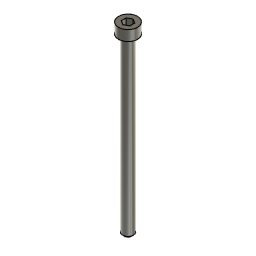
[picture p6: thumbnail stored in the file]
sketch "Sketch1" plane through (0, 0, 0) normal (0, 1, 0) x axis (1, 0, 0)
  line L1 (0, 50) -> (0, -3)
  line L2 (1.05, 50) -> (0, 50)
  line L3 (1.55, 49.5) -> (1.05, 50)
  line L4 (1.55, 0) -> (1.55, 49.5)
  line L5 (2.75, 0) -> (1.55, 0)
  line L6 (2.75, -3) -> (2.75, 0)
  line L7 (0, -3) -> (2.75, -3)
  point P1 (0, 0)
  point P4 (1.05, 50)
  point P5 (1.55, 49.5)
  point P3 (0, 50)
  point P7 (2.75, 0)
  point P8 (2.75, -3)
  point P2 (0, -3)
  vertical L1
  perpendicular L1 L2
  perpendicular L2 L4
  perpendicular L4 L5
  perpendicular L5 L6
  horizontal L7
  coincident P1 L1
  coincident P1 L5
  dimension "d1" distance P1 L2 = 50
  dimension "d2" angle L2 L3 = 45
  dimension "d3" distance P4 P5 = 0.5
  dimension "d4" distance P3 L4 = 1.55 (= "( 3.1 / 2 ) * 1 mm")
  dimension "d5" distance P7 P8 = 3
  dimension "d6" distance P2 P8 = 2.75 (= "( 5.5 / 2 ) * 1 mm")
revolve "Revolve1" sketch "Sketch1" AlongAngle 360
sketch "Sketch2" plane through (0, 0, 3) normal (0, 0, 1) x axis (-1, 0, 0)
  line L1 (0, -1.4434) -> (-1.25, -0.7217)
  line L2 (1.25, -0.7217) -> (0, -1.4434)
  line L3 (1.25, 0.7217) -> (1.25, -0.7217)
  line L4 (0, 1.4434) -> (1.25, 0.7217)
  line L5 (-1.25, 0.7217) -> (0, 1.4434)
  line L6 (-1.25, -0.7217) -> (-1.25, 0.7217)
  circle C1 centre (0, 0) radius 2.75
  point P1 (0, 0)
  point P9 (0, 0)
  point P5 (1.25, -0.7217)
  coincident P1 P9
  vertical L6
  dimension "d8" distance P5 L6 = 2.5
extrude "Extrude1" cut sketch "Sketch2" profile of L1 L2 L3 L4 L5 L6 against normal blind 2

design "PP_SWTC_Omron-V154"
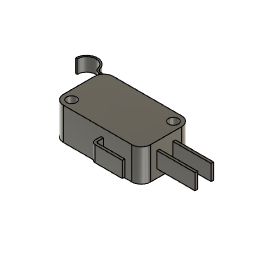
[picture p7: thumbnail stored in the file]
sketch "Sketch1" plane through (0, 0, 0) normal (0, 0, 1) x axis (1, 0, 0)
  line L1 (22.2, 0) -> (0, 0)
  line L2 (22.2, 10.3) -> (22.2, 0)
  line L3 (0, 10.3) -> (22.2, 10.3)
  line L4 (0, 0) -> (0, 10.3)
  line L5 (25, -2.8) -> (-2.8, -2.8)
  line L6 (25, 13.1) -> (25, -2.8)
  line L7 (-2.8, 13.1) -> (25, 13.1)
  line L8 (-2.8, -2.8) -> (-2.8, 13.1)
  line L9 (14.1, 15.2) -> (14.1, 13.1)
  line L10 (-6.9, 15.2) -> (14.1, 15.2)
  line L11 (13.6, 14.7) -> (-7.442, 14.7)
  line L12 (13.6, 13.1) -> (13.6, 14.7)
  line L13 (-13.9, 15.2) -> (-13.4, 15.2)
  line L14 (-10.4, 18.7) -> (-10.4, 15.2)
  line L15 (37.2, 8.1) -> (25, 8.1)
  line L16 (37.2, 7.3) -> (37.2, 8.1)
  line L17 (25, 7.3) -> (37.2, 7.3)
  line L18 (25, 8.1) -> (25, 7.3)
  line L19 (37.2, 3) -> (25, 3)
  line L20 (37.2, 2.2) -> (37.2, 3)
  line L21 (25, 2.2) -> (37.2, 2.2)
  line L22 (25, 3) -> (25, 2.2)
  line L23 (13, -5.2) -> (13, -2.8)
  line L24 (22.2, -5.2) -> (13, -5.2)
  line L25 (22.2, -6) -> (22.2, -5.2)
  line L26 (12.2, -6) -> (22.2, -6)
  line L27 (12.2, -2.8) -> (12.2, -6)
  circle C1 centre (0, 0) radius 2.8
  circle C2 centre (22.2, 10.3) radius 2.8
  circle C3 centre (22.2, 10.3) radius 1.55
  circle C4 centre (0, 0) radius 1.55
  arc A1 centre (-10.4, 15.2) radius 3.5 clockwise from (-13.9, 15.2) to (-6.9, 15.2)
  arc A2 centre (-10.4, 15.2) radius 3 clockwise from (-13.4, 15.2) to (-7.442, 14.7)
  point P1 (0, 0)
  point P2 (0, 0)
  point P10 (0, 0)
  point P4 (22.2, 10.3)
  point P11 (22.2, 10.3)
  point P13 (0, 0)
  point P14 (14.1, 13.1)
  point P18 (-13.9, 15.2)
  point P17 (-10.4, 15.2)
  point P19 (-10.4, 15.2)
  point P23 (13.6, 13.1)
  point P24 (-10.4, 15.2)
  point P25 (-10.4, 18.7)
  point P26 (25, 8.1)
  point P30 (25, 3)
  point P34 (13, -2.8)
  point P39 (12.2, -2.8)
  point P31 (37.2, 3)
  point P3 (22.2, 0)
  point P6 (-2.8, -2.8)
  point P7 (25, -2.8)
  point P9 (-2.8, 13.1)
  point P8 (25, 13.1)
  point P12 (22.2, 10.3)
  point P22 (13.6, 14.7)
  point P15 (14.1, 15.2)
  point P35 (13, -5.2)
  point P32 (37.2, 2.2)
  point P27 (37.2, 8.1)
  point P28 (37.2, 7.3)
  point P37 (22.2, -6)
  horizontal L1
  vertical L2
  horizontal L3
  vertical L4
  coincident P1 P2
  horizontal L5
  vertical L6
  horizontal L7
  vertical L8
  coincident P1 P10
  coincident P4 P11
  concentric C2 C3
  coincident P1 P13
  equal C3 C4
  tangent L7 C2
  tangent L6 C2
  tangent L5 C1
  coincident L7 P14
  perpendicular L7 L9
  perpendicular L9 L10
  coincident L10 P18
  coincident P17 P19
  horizontal L11
  coincident L7 P23
  perpendicular L7 L12
  coincident P19 L13
  horizontal L13
  coincident P19 P24
  midpoint A1 P25
  horizontal L15
  vertical L16
  horizontal L17
  vertical L18
  coincident L6 P26
  horizontal L19
  vertical L20
  horizontal L21
  vertical L22
  coincident L6 P30
  coincident L5 P34
  perpendicular L5 L23
  perpendicular L6 L24
  perpendicular L24 L25
  perpendicular L25 L26
  coincident L5 P39
  perpendicular L5 L27
  coincident L16 P31
  dimension "d2" distance P2 P3 = 22.2
  dimension "d3" distance P3 P4 = 10.3
  dimension "d4" distance P6 P7 = 27.8
  dimension "d5" distance P6 P9 = 15.9
  dimension "d6" diameter C3 = 3.1
  dimension "d7" distance P8 P12 = 2.8
  dimension "d8" distance L9 L12 = 0.5
  dimension "d9" distance L10 P22 = 0.5 (= "d8")
  dimension "d10" distance A1 A2 = 0.5 (= "d8")
  dimension "d11" radius A1 = 3.5
  dimension "d12" distance P10 P25 = 18.7
  dimension "d13" distance P12 P25 = 32.6
  dimension "d14" distance P12 P15 = 8.1
  dimension "d25" distance P35 L27 = 0.8
  dimension "d26" distance P35 L26 = 0.8 (= "d25")
  dimension "d27" distance P31 P32 = 0.8 (= "d25")
  dimension "d28" distance P27 P28 = 0.8 (= "d25")
  dimension "d29" distance P8 P37 = 19.1
  dimension "d30" distance P7 P37 = 2.8
  dimension "d31" distance P7 L23 = 12
  dimension "d33" distance P8 P27 = 5
  dimension "d34" distance P6 P28 = 40
  dimension "d35" distance P7 P32 = 5 (= "d33")
extrude "Extrude1" new body sketch "Sketch1" profile of L5 L6 L7 L8 C3 C4 distance 10.3
extrude "Extrude2" add sketch "Sketch1" profile of L7 L9 L10 A1 A2 L11 L12 L13 distance 4.3
fillet "Fillet1" radius 3
fillet "Fillet2" radius 1
fillet "Fillet3" radius 1.5
extrude "Extrude3" add sketch "Sketch1" profile of L5 L6 L15 L16 L17 L18 L19 L20 L21 L22 L23 L24 L25 L26 L27 distance 5
fillet "Fillet4" radius 0.5
fillet "Fillet5" radius 1.3 (= "0.5 mm + 0.8 mm")

design "HW_M3-Washer"
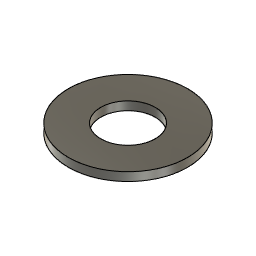
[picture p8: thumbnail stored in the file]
sketch "Sketch1" plane through (0, 0, 0) normal (0, 1, 0) x axis (1, 0, 0)
  line L1 (3.5, 0) -> (1.6, 0)
  line L2 (3.5, -0.5) -> (3.5, 0)
  line L3 (1.6, -0.5) -> (3.5, -0.5)
  line L4 (1.6, 0) -> (1.6, -0.5)
  point P1 (0, 0)
  point P2 (1.6, 0)
  point P5 (1.6, -0.5)
  horizontal L1
  vertical L2
  horizontal L3
  vertical L4
  coincident P1 L1
  dimension "d1" distance P2 P5 = 0.5
  dimension "d2" distance P1 L4 = 1.6 (= "( 3.2 / 2 ) * 1 mm")
  dimension "d3" distance P1 L2 = 3.5 (= "( 7 / 2 ) * 1 mm")
revolve "Revolve1" sketch "Sketch1" AlongAngle 360

design "PP_TRNS_GT2-Pulley-20T-6mm"
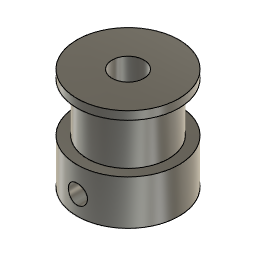
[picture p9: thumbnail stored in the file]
sketch "Sketch1" plane through (0, 0, 0) normal (0, 1, 0) x axis (1, 0, 0)
  line L1 (8, 0) -> (0, 0)
  line L2 (8, -7) -> (8, 0)
  line L3 (6.3662, -7) -> (8, -7)
  line L4 (6.3662, -14.7) -> (6.3662, -7)
  line L5 (8, -14.7) -> (6.3662, -14.7)
  line L6 (8, -16) -> (8, -14.7)
  line L7 (2.5, -16) -> (8, -16)
  line L8 (2.5, 0) -> (2.5, -16)
  line L9 (0, -3) -> (0, 0)
  circle C1 centre (0, -3) radius 1.5
  point P1 (0, 0)
  point P2 (0, 0)
  point P10 (2.5, 0)
  point P4 (8, -7)
  point P12 (0, 0)
  point P11 (0, -3)
  point P13 (0, -3)
  point P3 (8, 0)
  point P7 (8, -14.7)
  point P8 (8, -16)
  coincident P1 P2
  horizontal L1
  perpendicular L1 L2
  perpendicular L2 L3
  perpendicular L3 L4
  perpendicular L4 L5
  perpendicular L5 L6
  perpendicular L4 L7
  coincident L1 P10
  perpendicular L1 L8
  coincident P4 L6
  coincident P1 P12
  coincident P11 P13
  vertical L9
  dimension "d1" distance P1 L8 = 2.5 (= "( 5 / 2 ) * 1 mm")
  dimension "d2" distance P1 L2 = 8 (= "( 16 / 2 ) * 1 mm")
  dimension "d3" distance P3 P4 = 7
  dimension "d4" distance P1 L4 = 6.3662 (= "( 20 * 2 / PI ) * 1 mm / 2")
  dimension "d5" distance P7 P8 = 1.3
  dimension "d6" distance P3 L7 = 16
  dimension "d8" diameter C1 = 3
  dimension "d9" distance P12 P13 = 3
revolve "Revolve1" sketch "Sketch1" AlongAngle 360
extrude "Extrude1" cut sketch "Sketch1" profile of C1 against normal blind 17

design "PP_BRNG_6808-40x52x7"
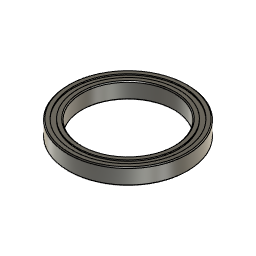
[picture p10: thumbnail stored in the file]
sketch "Sketch1" plane through (0, 0, 0) normal (0, 1, 0) x axis (1, 0, 0)
  line L1 (22, -3.5) -> (20, -3.5)
  line L2 (20, 3.5) -> (22, 3.5)
  line L3 (20, -3.5) -> (20, 3.5)
  line L4 (26, -3.5) -> (24, -3.5)
  line L5 (26, 3.5) -> (26, -3.5)
  line L6 (24, 3.5) -> (26, 3.5)
  line L7 (24, -3) -> (22, -3)
  line L8 (24, 3) -> (22, 3)
  line L9 (22, -3) -> (22, -3.5)
  line L10 (22, 3.5) -> (22, 3)
  line L11 (24, 3) -> (24, 3.5)
  line L12 (24, -3.5) -> (24, -3)
  line L13 (0, 0) -> (26, 0)
  point P11 (24, -3)
  point P12 (22, 3)
  point P14 (26, 0)
  point P1 (0, 0)
  point P15 (0, 0)
  point P16 (20, 0)
  point P6 (24, -3.5)
  point P2 (20, -3.5)
  point P3 (22, -3.5)
  point P10 (22, -3)
  point P7 (26, -3.5)
  point P8 (26, 3.5)
  horizontal L1
  vertical L9
  horizontal L2
  vertical L3
  horizontal L4
  vertical L5
  horizontal L6
  vertical L11
  coincident P11 L11
  perpendicular L7 L11
  coincident P12 L9
  perpendicular L8 L9
  collinear L9 L10
  collinear L11 L12
  midpoint L5 P14
  coincident P1 P15
  horizontal L13
  midpoint L3 P16
  coincident L13 P16
  equal L1 L4
  equal L9 L10
  coincident L1 P6
  dimension "d1" distance P1 L3 = 20 (= "( 40 / 2 ) * 1 mm")
  dimension "d3" distance P2 P3 = 2
  dimension "d4" distance P3 P10 = 0.5
  dimension "d5" distance P7 P8 = 7
  dimension "d8" distance P1 L5 = 26 (= "( 52 / 2 ) * 1 mm")
revolve "Revolve1" sketch "Sketch1" AlongAngle 360
chamfer "Chamfer1" distance 0.4

design "HW_M3x16-SHCS"
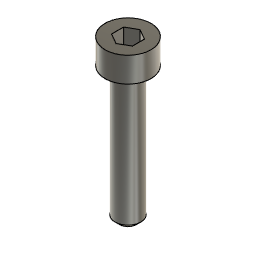
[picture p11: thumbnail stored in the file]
sketch "Sketch1" plane through (0, 0, 0) normal (0, 1, 0) x axis (1, 0, 0)
  line L1 (0, 16) -> (0, -3)
  line L2 (1.05, 16) -> (0, 16)
  line L3 (1.55, 15.5) -> (1.05, 16)
  line L4 (1.55, 0) -> (1.55, 15.5)
  line L5 (2.75, 0) -> (1.55, 0)
  line L6 (2.75, -3) -> (2.75, 0)
  line L7 (0, -3) -> (2.75, -3)
  point P1 (0, 0)
  point P4 (1.05, 16)
  point P5 (1.55, 15.5)
  point P3 (0, 16)
  point P7 (2.75, 0)
  point P8 (2.75, -3)
  point P2 (0, -3)
  vertical L1
  perpendicular L1 L2
  perpendicular L2 L4
  perpendicular L4 L5
  perpendicular L5 L6
  horizontal L7
  coincident P1 L1
  coincident P1 L5
  dimension "d1" distance P1 L2 = 16
  dimension "d2" angle L2 L3 = 45
  dimension "d3" distance P4 P5 = 0.5
  dimension "d4" distance P3 L4 = 1.55 (= "( 3.1 / 2 ) * 1 mm")
  dimension "d5" distance P7 P8 = 3
  dimension "d6" distance P2 P8 = 2.75 (= "( 5.5 / 2 ) * 1 mm")
revolve "Revolve1" sketch "Sketch1" AlongAngle 360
